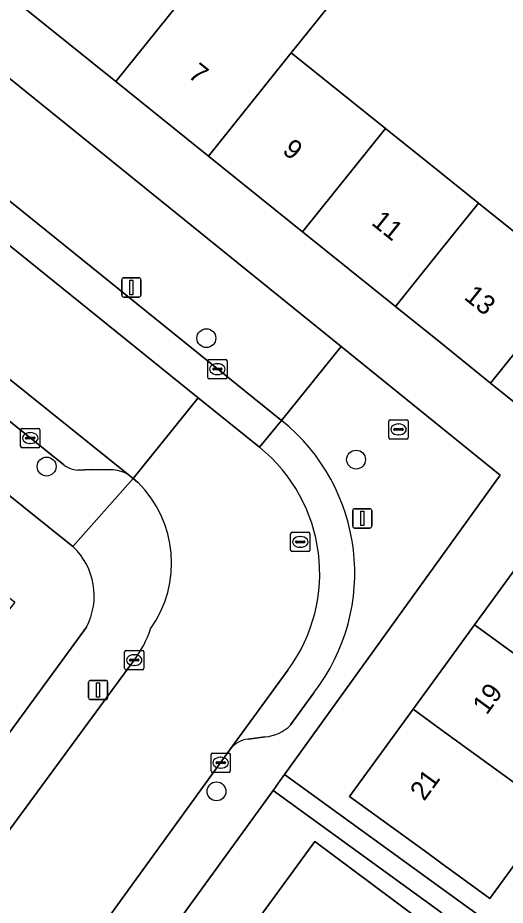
# Model space of a CAD drawing. Extents: x 160102 to 160934, y 382045 to 382923.
# Drawn here: x 160478.07 to 160503.34, y 382536.21 to 382582.18 of the extents above; entities that cross this region are included whole.
import ezdxf

# ---------------------------------------------------------------- set-up
doc = ezdxf.new("R2010")
doc.units = 0
for name, color, linetype in [('IMGEO_Boom', 7, 'Continuous'), ('IMGEO_Brandkraan', 7, 'Continuous'), ('IMGEO_Erf', 7, 'Continuous'), ('IMGEO_Groenvoorziening', 7, 'Continuous'), ('IMGEO_Kolk', 7, 'Continuous'), ('IMGEO_Lichtmast', 7, 'Continuous'), ('IMGEO_Pand', 7, 'Continuous'), ('IMGEO_Pand_nummerreeks', 7, 'Continuous'), ('IMGEO_Parkeervlak_open', 7, 'Continuous'), ('IMGEO_Rijbaan_lokaal_open', 7, 'Continuous'), ('IMGEO_Rioolput', 7, 'Continuous'), ('IMGEO_Voetpad_open', 7, 'Continuous')]:
    doc.layers.add(name, color=color, linetype=linetype)

msp = doc.modelspace()

# ---------------------------------------------------------------- linework, layer by layer
at = {"layer": 'IMGEO_Boom'}
for centre in [(160487.844, 382565.584), (160479.567, 382558.934), (160495.604, 382559.293), (160488.37, 382542.112)]:
    msp.add_circle(centre, 0.489, dxfattribs=at)
at = {"layer": 'IMGEO_Brandkraan'}
for p, q in [((160497.304, 382560.433), (160497.304, 382561.285)), ((160497.379, 382561.359), (160498.231, 382561.359)), ((160498.305, 382561.285), (160498.305, 382560.433)), ((160497.563, 382560.853), (160497.563, 382560.865)), ((160498.001, 382560.816), (160497.603, 382560.816)), ((160497.606, 382560.902), (160498.004, 382560.902)), ((160497.792, 382561.139), (160497.817, 382561.139)), ((160498.047, 382560.865), (160498.047, 382560.853)), ((160498.231, 382560.359), (160497.379, 382560.359)), ((160497.815, 382560.579), (160497.79, 382560.579))]:
    msp.add_line(p, q, dxfattribs=at)
for points in [[(160497.304, 382560.433), (160497.304, 382561.285)], [(160497.379, 382561.359), (160498.231, 382561.359)], [(160498.305, 382561.285), (160498.305, 382560.433)], [(160498.231, 382560.359), (160497.379, 382560.359)]]:
    msp.add_lwpolyline(points, dxfattribs=at)
for centre, radius, start, end in [((160497.381, 382561.283), 0.0765, 91.552, 178.448), ((160497.381, 382561.283), 0.0765, 91.552, 178.448), ((160498.229, 382561.283), 0.0765, 1.552, 88.448), ((160498.229, 382561.283), 0.0765, 1.552, 88.448), ((160497.603, 382560.862), 0.0403, 85.8775, 175.7526), ((160497.6, 382560.852), 0.0366, 178.938, 274.7102), ((160498.004, 382560.859), 0.043, 264.8664, 352.4533), ((160498.008, 382560.864), 0.0386, 1.7309, 96.639), ((160497.381, 382560.435), 0.0765, 181.552, 268.448), ((160497.381, 382560.435), 0.0765, 181.552, 268.448), ((160498.229, 382560.435), 0.0765, 271.552, 358.448), ((160498.229, 382560.435), 0.0765, 271.552, 358.448)]:
    msp.add_arc(centre, radius, start, end, dxfattribs=at)
for centre, major_axis, ratio, start_param, end_param in [((160497.791, 382560.859), (-0.387, 0.002), 0.722429, 4.712389, 7.853982), ((160497.816, 382560.859), (-0.39, 0.002), 0.717154, 1.570796, 4.712389)]:
    msp.add_ellipse(centre, major_axis=major_axis, ratio=ratio, start_param=start_param, end_param=end_param, dxfattribs=at)
at = {"layer": 'IMGEO_Erf'}
for points in [[(160466.307, 382588.202), (160494.827, 382565.152), (160500, 382560.972), (160503.073, 382558.488), (160500, 382554.224), (160491.895, 382542.979), (160500, 382537.111), (160512.903, 382527.769), (160513.795, 382534.731), (160510.825, 382535.221), (160511.14, 382537.129), (160511.461, 382539.075), (160514.431, 382538.585), (160515.795, 382546.76), (160513.821, 382547.08), (160514.301, 382550.045), (160516.275, 382549.725), (160519.19, 382547.212), (160517.912, 382530.251), (160515.877, 382500), (160513.04, 382457.812)], [(160494.172, 382582.757), (160492.247, 382580.362), (160497.131, 382576.442), (160500, 382574.14), (160501.942, 382572.581), (160506.884, 382568.616), (160511.788, 382564.68), (160513.923, 382567.267), (160520.438, 382566.776), (160512.167, 382556.49), (160507.938, 382559.891), (160507.48, 382559.322), (160502.579, 382563.261), (160500, 382565.334), (160497.641, 382567.23), (160492.833, 382571.095), (160487.952, 382575.018), (160483.149, 382578.878), (160478.25, 382582.816)], [(160500, 382535.855), (160491.302, 382542.157), (160460.502, 382499.766)], [(160489.69, 382534.336), (160493.459, 382539.514), (160497.473, 382536.533), (160498.98, 382535.413)]]:
    msp.add_lwpolyline(points, dxfattribs=at)
msp.add_lwpolyline([(160505.83, 382541.082), (160502.541, 382536.567), (160500, 382538.411), (160499.319, 382538.905), (160495.271, 382541.842), (160498.564, 382546.369), (160500, 382548.343), (160501.74, 382550.735), (160505.035, 382555.264), (160509.068, 382552.309), (160512.289, 382549.95), (160509.011, 382545.449)], close=True, dxfattribs=at)
at = {"layer": 'IMGEO_Groenvoorziening'}
msp.add_lwpolyline([(160480.93, 382554.797), (160474.597, 382559.852), (160472.193, 382556.489), (160477.92, 382551.918), (160475.89, 382549.359), (160476.041, 382549.232), (160474.889, 382547.817), (160474.685, 382547.989), (160471.372, 382543.84), (160467.464, 382546.959), (160466.305, 382547.884), (160464.448, 382545.248), (160472.063, 382539.302), (160472.614, 382539.022), (160472.982, 382539.015), (160473.289, 382539.215), (160481.629, 382550.609)], dxfattribs=at)
msp.add_arc((160478.52, 382552.242), 3.512, 332.2826, 46.6687, dxfattribs=at)
at = {"layer": 'IMGEO_Kolk'}
for p, q in [((160487.99, 382564.48), (160488.842, 382564.48)), ((160487.915, 382563.554), (160487.915, 382564.406)), ((160488.174, 382563.974), (160488.174, 382563.986)), ((160488.217, 382564.023), (160488.615, 382564.023)), ((160488.403, 382564.26), (160488.428, 382564.26)), ((160488.658, 382563.986), (160488.658, 382563.974)), ((160488.916, 382564.406), (160488.916, 382563.554)), ((160488.612, 382563.937), (160488.214, 382563.937)), ((160488.426, 382563.7), (160488.401, 382563.7)), ((160488.842, 382563.48), (160487.99, 382563.48)), ((160478.217, 382559.984), (160478.217, 382560.836)), ((160478.292, 382560.91), (160479.144, 382560.91)), ((160479.218, 382560.836), (160479.218, 382559.984)), ((160478.476, 382560.404), (160478.476, 382560.416)), ((160478.914, 382560.367), (160478.516, 382560.367)), ((160478.519, 382560.453), (160478.917, 382560.453)), ((160478.705, 382560.69), (160478.73, 382560.69)), ((160478.96, 382560.416), (160478.96, 382560.404)), ((160479.144, 382559.91), (160478.292, 382559.91)), ((160478.728, 382560.13), (160478.703, 382560.13)), ((160483.606, 382548.484), (160483.606, 382549.336)), ((160483.681, 382549.41), (160484.533, 382549.41)), ((160484.607, 382549.336), (160484.607, 382548.484)), ((160483.865, 382548.904), (160483.865, 382548.916)), ((160484.303, 382548.867), (160483.905, 382548.867)), ((160483.908, 382548.953), (160484.306, 382548.953)), ((160484.094, 382549.19), (160484.119, 382549.19)), ((160484.349, 382548.916), (160484.349, 382548.904)), ((160484.533, 382548.41), (160483.681, 382548.41)), ((160484.117, 382548.63), (160484.092, 382548.63)), ((160488.086, 382543.169), (160488.086, 382544.021)), ((160488.161, 382544.095), (160489.013, 382544.095)), ((160488.574, 382543.875), (160488.599, 382543.875)), ((160489.087, 382544.021), (160489.087, 382543.169)), ((160488.345, 382543.589), (160488.345, 382543.601)), ((160488.783, 382543.552), (160488.385, 382543.552)), ((160488.388, 382543.638), (160488.786, 382543.638)), ((160488.597, 382543.315), (160488.572, 382543.315)), ((160488.829, 382543.601), (160488.829, 382543.589)), ((160489.013, 382543.095), (160488.161, 382543.095))]:
    msp.add_line(p, q, dxfattribs=at)
for points in [[(160487.99, 382564.48), (160488.842, 382564.48)], [(160487.915, 382563.554), (160487.915, 382564.406)], [(160488.916, 382564.406), (160488.916, 382563.554)], [(160488.842, 382563.48), (160487.99, 382563.48)], [(160478.217, 382559.984), (160478.217, 382560.836)], [(160478.292, 382560.91), (160479.144, 382560.91)], [(160479.218, 382560.836), (160479.218, 382559.984)], [(160479.144, 382559.91), (160478.292, 382559.91)], [(160483.606, 382548.484), (160483.606, 382549.336)], [(160483.681, 382549.41), (160484.533, 382549.41)], [(160484.607, 382549.336), (160484.607, 382548.484)], [(160484.533, 382548.41), (160483.681, 382548.41)], [(160488.086, 382543.169), (160488.086, 382544.021)], [(160488.161, 382544.095), (160489.013, 382544.095)], [(160489.087, 382544.021), (160489.087, 382543.169)], [(160489.013, 382543.095), (160488.161, 382543.095)]]:
    msp.add_lwpolyline(points, dxfattribs=at)
for centre, radius, start, end in [((160487.992, 382564.404), 0.0765, 91.552, 178.448), ((160487.992, 382564.404), 0.0765, 91.552, 178.448), ((160488.84, 382564.404), 0.0765, 1.552, 88.448), ((160488.84, 382564.404), 0.0765, 1.552, 88.448), ((160488.214, 382563.983), 0.0403, 85.8775, 175.7526), ((160488.211, 382563.973), 0.0366, 178.938, 274.7102), ((160488.615, 382563.98), 0.043, 264.8664, 352.4533), ((160488.619, 382563.985), 0.0386, 1.7309, 96.639), ((160487.992, 382563.556), 0.0765, 181.552, 268.448), ((160487.992, 382563.556), 0.0765, 181.552, 268.448), ((160488.84, 382563.556), 0.0765, 271.552, 358.448), ((160488.84, 382563.556), 0.0765, 271.552, 358.448), ((160478.294, 382560.834), 0.0765, 91.552, 178.448), ((160478.294, 382560.834), 0.0765, 91.552, 178.448), ((160479.142, 382560.834), 0.0765, 1.552, 88.448), ((160479.142, 382560.834), 0.0765, 1.552, 88.448), ((160478.516, 382560.413), 0.0403, 85.8775, 175.7526), ((160478.513, 382560.403), 0.0366, 178.938, 274.7102), ((160478.917, 382560.41), 0.043, 264.8664, 352.4533), ((160478.921, 382560.415), 0.0386, 1.7309, 96.639), ((160478.294, 382559.986), 0.0765, 181.552, 268.448), ((160478.294, 382559.986), 0.0765, 181.552, 268.448), ((160479.142, 382559.986), 0.0765, 271.552, 358.448), ((160479.142, 382559.986), 0.0765, 271.552, 358.448), ((160483.683, 382549.334), 0.0765, 91.552, 178.448), ((160483.683, 382549.334), 0.0765, 91.552, 178.448), ((160484.531, 382549.334), 0.0765, 1.552, 88.448), ((160484.531, 382549.334), 0.0765, 1.552, 88.448), ((160483.905, 382548.913), 0.0403, 85.8775, 175.7526), ((160483.902, 382548.903), 0.0366, 178.938, 274.7102), ((160484.306, 382548.91), 0.043, 264.8664, 352.4533), ((160484.31, 382548.915), 0.0386, 1.7309, 96.639), ((160483.683, 382548.486), 0.0765, 181.552, 268.448), ((160483.683, 382548.486), 0.0765, 181.552, 268.448), ((160484.531, 382548.486), 0.0765, 271.552, 358.448), ((160484.531, 382548.486), 0.0765, 271.552, 358.448), ((160488.163, 382544.019), 0.0765, 91.552, 178.448), ((160488.163, 382544.019), 0.0765, 91.552, 178.448), ((160489.011, 382544.019), 0.0765, 1.552, 88.448), ((160489.011, 382544.019), 0.0765, 1.552, 88.448), ((160488.385, 382543.598), 0.0403, 85.8775, 175.7526), ((160488.382, 382543.588), 0.0366, 178.938, 274.7102), ((160488.786, 382543.595), 0.043, 264.8664, 352.4533), ((160488.79, 382543.6), 0.0386, 1.7309, 96.639), ((160488.163, 382543.171), 0.0765, 181.552, 268.448), ((160488.163, 382543.171), 0.0765, 181.552, 268.448), ((160489.011, 382543.171), 0.0765, 271.552, 358.448), ((160489.011, 382543.171), 0.0765, 271.552, 358.448)]:
    msp.add_arc(centre, radius, start, end, dxfattribs=at)
for centre, major_axis, ratio, start_param, end_param in [((160488.402, 382563.98), (-0.387, 0.002), 0.722429, 4.712389, 7.853982), ((160488.427, 382563.98), (-0.39, 0.002), 0.717154, 1.570796, 4.712389), ((160478.704, 382560.41), (-0.387, 0.002), 0.722429, 4.712389, 7.853982), ((160478.729, 382560.41), (-0.39, 0.002), 0.717154, 1.570796, 4.712389), ((160484.093, 382548.91), (-0.387, 0.002), 0.722429, 4.712389, 7.853982), ((160484.118, 382548.91), (-0.39, 0.002), 0.717154, 1.570796, 4.712389), ((160488.573, 382543.595), (-0.387, 0.002), 0.722429, 4.712389, 7.853982), ((160488.598, 382543.595), (-0.39, 0.002), 0.717154, 1.570796, 4.712389)]:
    msp.add_ellipse(centre, major_axis=major_axis, ratio=ratio, start_param=start_param, end_param=end_param, dxfattribs=at)
at = {"layer": 'IMGEO_Lichtmast'}
for p, q in [((160483.461, 382567.809), (160483.461, 382568.609)), ((160483.461, 382568.609), (160483.461, 382567.809)), ((160483.561, 382568.709), (160484.351, 382568.709)), ((160484.351, 382568.709), (160483.561, 382568.709)), ((160484.451, 382568.609), (160484.451, 382567.809)), ((160484.451, 382567.809), (160484.451, 382568.609)), ((160484.351, 382567.709), (160483.561, 382567.709)), ((160483.561, 382567.709), (160484.351, 382567.709)), ((160495.429, 382555.852), (160495.429, 382556.652)), ((160495.429, 382556.652), (160495.429, 382555.852)), ((160495.529, 382556.752), (160496.319, 382556.752)), ((160496.319, 382556.752), (160495.529, 382556.752)), ((160496.419, 382556.652), (160496.419, 382555.852)), ((160496.419, 382555.852), (160496.419, 382556.652)), ((160496.319, 382555.752), (160495.529, 382555.752)), ((160495.529, 382555.752), (160496.319, 382555.752)), ((160481.738, 382546.962), (160481.738, 382547.762)), ((160481.738, 382547.762), (160481.738, 382546.962)), ((160481.838, 382547.862), (160482.628, 382547.862)), ((160482.628, 382547.862), (160481.838, 382547.862)), ((160482.728, 382547.762), (160482.728, 382546.962)), ((160482.728, 382546.962), (160482.728, 382547.762)), ((160482.628, 382546.862), (160481.838, 382546.862)), ((160481.838, 382546.862), (160482.628, 382546.862))]:
    msp.add_line(p, q, dxfattribs=at)
for points in [[(160483.881, 382568.584), (160484.031, 382568.584), (160484.031, 382567.834), (160483.881, 382567.834), (160483.881, 382568.584)], [(160495.849, 382556.627), (160495.999, 382556.627), (160495.999, 382555.877), (160495.849, 382555.877), (160495.849, 382556.627)], [(160482.158, 382547.737), (160482.308, 382547.737), (160482.308, 382546.987), (160482.158, 382546.987), (160482.158, 382547.737)]]:
    msp.add_lwpolyline(points, dxfattribs=at)
for centre, start, end in [((160483.561, 382568.609), 90, 180), ((160483.561, 382568.609), 90, 180), ((160484.351, 382568.609), 0, 90), ((160484.351, 382568.609), 360, 90), ((160483.561, 382567.809), 180, 270), ((160483.561, 382567.809), 180, 270), ((160484.351, 382567.809), 270, 0), ((160484.351, 382567.809), 270, 0), ((160495.529, 382556.652), 90, 180), ((160495.529, 382556.652), 90, 180), ((160496.319, 382556.652), 0, 90), ((160496.319, 382556.652), 360, 90), ((160495.529, 382555.852), 180, 270), ((160495.529, 382555.852), 180, 270), ((160496.319, 382555.852), 270, 0), ((160496.319, 382555.852), 270, 0), ((160481.838, 382547.762), 90, 180), ((160481.838, 382547.762), 90, 180), ((160482.628, 382547.762), 0, 90), ((160482.628, 382547.762), 360, 90), ((160481.838, 382546.962), 180, 270), ((160481.838, 382546.962), 180, 270), ((160482.628, 382546.962), 270, 0), ((160482.628, 382546.962), 270, 0)]:
    msp.add_arc(centre, 0.1, start, end, dxfattribs=at)
at = {"layer": 'IMGEO_Pand'}
for points in [[(160483.149, 382578.878), (160487.442, 382584.218), (160482.54, 382588.152), (160478.25, 382582.816)], [(160492.247, 382580.362), (160494.172, 382582.757), (160489.365, 382586.621), (160487.442, 382584.218), (160483.149, 382578.878), (160487.952, 382575.018)], [(160492.833, 382571.095), (160497.131, 382576.442), (160492.247, 382580.362), (160487.952, 382575.018)], [(160492.833, 382571.095), (160497.641, 382567.23), (160500, 382570.165), (160501.942, 382572.581), (160500, 382574.14), (160497.131, 382576.442)], [(160502.579, 382563.261), (160506.884, 382568.616), (160501.942, 382572.581), (160500, 382570.165), (160497.641, 382567.23), (160500, 382565.334)], [(160511.788, 382564.68), (160506.884, 382568.616), (160502.579, 382563.261), (160507.48, 382559.322), (160507.938, 382559.891), (160510.614, 382563.219)], [(160509.011, 382545.449), (160512.289, 382549.95), (160509.068, 382552.309), (160505.035, 382555.264), (160501.74, 382550.735)], [(160498.564, 382546.369), (160500, 382545.324), (160505.83, 382541.082), (160509.011, 382545.449), (160501.74, 382550.735), (160500, 382548.343)], [(160498.564, 382546.369), (160495.271, 382541.842), (160499.319, 382538.905), (160500, 382538.411), (160502.541, 382536.567), (160505.83, 382541.082), (160500, 382545.324)], [(160498.803, 382535.169), (160498.98, 382535.413), (160497.473, 382536.533), (160493.459, 382539.514), (160489.69, 382534.336), (160495.25, 382530.289), (160497.697, 382528.508), (160501.249, 382533.388)]]:
    msp.add_lwpolyline(points, close=True, dxfattribs=at)
at = {"layer": 'IMGEO_Parkeervlak_open'}
for points in [[(160483.799, 382558.523), (160450.577, 382585.198), (160437.847, 382595.414)], [(160438.907, 382592.26), (160448.753, 382584.442), (160458.029, 382576.973), (160473.398, 382564.68), (160480.457, 382559.016)], [(160463.099, 382582.104), (160487.415, 382562.498), (160490.592, 382559.937), (160491.735, 382561.326), (160466.43, 382581.731)], [(160491.735, 382561.326), (160490.592, 382559.937)], [(160481.177, 382558.75), (160481.883, 382558.782), (160482.896, 382558.763)], [(160492.067, 382548.393), (160489.103, 382544.309)], [(160492.214, 382545.555), (160493.416, 382547.223)], [(160490.003, 382544.82), (160490.893, 382544.933)]]:
    msp.add_lwpolyline(points, dxfattribs=at)
for centre, radius, start, end in [((160485.409, 382553.42), 10.125, 322.2598, 51.3348), ((160485.315, 382553.397), 8.404, 323.4605, 51.1022), ((160481.299, 382560.189), 1.444, 234.3121, 265.1349), ((160482.881, 382556.886), 1.877, 60.7037, 89.5283), ((160490.72, 382547.015), 2.089, 274.7569, 315.6704), ((160490.169, 382543.479), 1.351, 97.0702, 142.1037)]:
    msp.add_arc(centre, radius, start, end, dxfattribs=at)
at = {"layer": 'IMGEO_Rijbaan_lokaal_open'}
for points in [[(160435.049, 382597.428), (160435.985, 382596.798), (160437.847, 382595.414), (160450.577, 382585.198), (160483.799, 382558.523), (160484.046, 382558.32), (160487.415, 382562.498), (160463.099, 382582.104)], [(160490.592, 382559.937), (160487.415, 382562.498), (160484.046, 382558.32), (160484.294, 382558.117)], [(160484.111, 382548.915), (160483.949, 382548.692), (160456.229, 382511.004), (160443.452, 382493.376), (160449.428, 382489.694), (160458.647, 382502.288), (160458.858, 382502.576), (160459.289, 382503.191), (160489.103, 382544.309)], [(160489.103, 382544.309), (160492.067, 382548.393)]]:
    msp.add_lwpolyline(points, dxfattribs=at)
for centre, radius, start, end in [((160485.315, 382553.397), 8.404, 323.4605, 51.1022), ((160480.17, 382553.936), 5.873, 324.497, 45.3949), ((160479.581, 382552.302), 5.656, 323.2094, 341.6849)]:
    msp.add_arc(centre, radius, start, end, dxfattribs=at)
at = {"layer": 'IMGEO_Rioolput'}
for p, q in [((160492.212, 382554.605), (160492.212, 382555.457)), ((160492.287, 382555.531), (160493.139, 382555.531)), ((160492.7, 382555.311), (160492.725, 382555.311)), ((160493.213, 382555.457), (160493.213, 382554.605)), ((160492.471, 382555.025), (160492.471, 382555.037)), ((160492.909, 382554.988), (160492.511, 382554.988)), ((160492.514, 382555.074), (160492.912, 382555.074)), ((160492.955, 382555.037), (160492.955, 382555.025)), ((160493.139, 382554.531), (160492.287, 382554.531)), ((160492.723, 382554.751), (160492.698, 382554.751))]:
    msp.add_line(p, q, dxfattribs=at)
for points in [[(160492.212, 382554.605), (160492.212, 382555.457)], [(160492.287, 382555.531), (160493.139, 382555.531)], [(160493.213, 382555.457), (160493.213, 382554.605)], [(160493.139, 382554.531), (160492.287, 382554.531)]]:
    msp.add_lwpolyline(points, dxfattribs=at)
for centre, radius, start, end in [((160492.289, 382555.455), 0.0765, 91.552, 178.448), ((160492.289, 382555.455), 0.0765, 91.552, 178.448), ((160493.137, 382555.455), 0.0765, 1.552, 88.448), ((160493.137, 382555.455), 0.0765, 1.552, 88.448), ((160492.511, 382555.034), 0.0403, 85.8775, 175.7526), ((160492.508, 382555.024), 0.0366, 178.938, 274.7102), ((160492.912, 382555.031), 0.043, 264.8664, 352.4533), ((160492.916, 382555.036), 0.0386, 1.7309, 96.639), ((160492.289, 382554.607), 0.0765, 181.552, 268.448), ((160492.289, 382554.607), 0.0765, 181.552, 268.448), ((160493.137, 382554.607), 0.0765, 271.552, 358.448), ((160493.137, 382554.607), 0.0765, 271.552, 358.448)]:
    msp.add_arc(centre, radius, start, end, dxfattribs=at)
for centre, major_axis, ratio, start_param, end_param in [((160492.699, 382555.031), (-0.387, 0.002), 0.722429, 4.712389, 7.853982), ((160492.724, 382555.031), (-0.39, 0.002), 0.717154, 1.570796, 4.712389)]:
    msp.add_ellipse(centre, major_axis=major_axis, ratio=ratio, start_param=start_param, end_param=end_param, dxfattribs=at)
at = {"layer": 'IMGEO_Voetpad_open'}
for points in [[(160466.43, 382581.731), (160491.735, 382561.326), (160494.827, 382565.152), (160466.307, 382588.202), (160462.972, 382590.915), (160446.842, 382603.909)], [(160433.113, 382587.311), (160445.752, 382577.45), (160446.881, 382576.57), (160448.152, 382575.578), (160450.852, 382578.804), (160459.072, 382572.243), (160461.271, 382570.488), (160472.502, 382561.524), (160474.597, 382559.852), (160480.93, 382554.797), (160484.046, 382558.32), (160483.799, 382558.523)], [(160480.457, 382559.016), (160473.398, 382564.68), (160458.029, 382576.973)], [(160491.302, 382542.157), (160491.676, 382542.675), (160491.895, 382542.979), (160500, 382554.224), (160503.073, 382558.488), (160500, 382560.972), (160494.827, 382565.152), (160491.735, 382561.326)], [(160482.896, 382558.763), (160481.883, 382558.782), (160481.177, 382558.75)], [(160484.294, 382558.117), (160484.046, 382558.32), (160480.93, 382554.797)], [(160481.629, 382550.609), (160473.289, 382539.215), (160472.07, 382537.55), (160444.564, 382500), (160440.163, 382493.992)], [(160483.949, 382548.692), (160484.111, 382548.915)], [(160443.22, 382493.058), (160443.452, 382493.376), (160456.229, 382511.004), (160483.949, 382548.692)], [(160493.416, 382547.223), (160492.214, 382545.555)], [(160490.893, 382544.933), (160490.003, 382544.82)], [(160489.103, 382544.309), (160459.289, 382503.191), (160460.043, 382502.691), (160459.374, 382501.781)], [(160512.903, 382527.769), (160500, 382537.111), (160491.895, 382542.979), (160491.676, 382542.675), (160491.302, 382542.157), (160500, 382535.855), (160508.888, 382529.416), (160500, 382517.229), (160492.218, 382506.559), (160487.432, 382500), (160482.415, 382493.1), (160478.803, 382488.076)], [(160458.886, 382498.142), (160460.502, 382499.766), (160491.302, 382542.157)]]:
    msp.add_lwpolyline(points, dxfattribs=at)
for centre, radius, start, end in [((160485.409, 382553.42), 10.125, 322.2598, 51.3348), ((160481.299, 382560.189), 1.444, 234.3121, 265.1349), ((160482.881, 382556.886), 1.877, 60.7037, 89.5283), ((160480.17, 382553.936), 5.873, 324.497, 45.3949), ((160478.52, 382552.242), 3.512, 332.2826, 46.6687), ((160479.581, 382552.302), 5.656, 323.2094, 341.6849), ((160490.72, 382547.015), 2.089, 274.7569, 315.6704), ((160490.169, 382543.479), 1.351, 97.0702, 142.1037)]:
    msp.add_arc(centre, radius, start, end, dxfattribs=at)

# ---------------------------------------------------------------- texts
at = {"layer": 'IMGEO_Pand_nummerreeks'}
for s, rotation, p in [('7', 321.2108, (160486.842, 382579.143)), ('9', 321.2091, (160491.731, 382575.214)), ('11', 321.2091, (160496.35, 382571.5)), ('13', 321.2091, (160501.151, 382567.642)), ('19', 53.9655, (160502.373, 382546.028)), ('21', 53.9655, (160499.131, 382541.572))]:
    msp.add_text(s, height=1, rotation=rotation, dxfattribs=at).set_placement(p)

doc.saveas('drawing.dxf')
